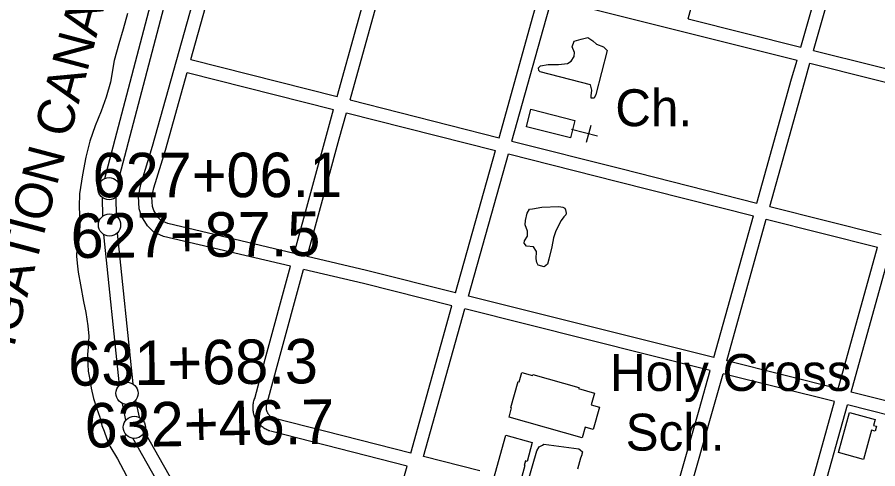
# Model space of a CAD drawing. Extents: x 3677843 to 3715951, y 511991 to 537744.
# Drawn here: x 3694073 to 3696008, y 532913 to 533929 of the extents above; entities that cross this region are included whole.
import ezdxf

# ---------------------------------------------------------------- set-up
doc = ezdxf.new("R2010")
doc.units = 0
for name, color, linetype in [('V-BLDG-IDEN', 7, 'Continuous'), ('V-BLDG-OTLN', 7, 'Continuous'), ('V-RIVR-IDEN', 7, 'Continuous'), ('V-ROAD-CNTR', 7, 'Continuous'), ('V-SITE-OTLN', 7, 'Continuous'), ('V-SITE-VEGE', 7, 'Continuous'), ('V-SURV-IDEN', 7, 'Continuous'), ('V-SURV-LINE', 7, 'Continuous'), ('V-TOPO-SHOR', 7, 'Continuous')]:
    doc.layers.add(name, color=color, linetype=linetype)

msp = doc.modelspace()

# ---------------------------------------------------------------- linework, layer by layer
at = {"layer": 'V-BLDG-OTLN'}
for points in [[(3695316.5, 533657.1), (3695217.7, 533682.2), (3695227.8, 533721.8), (3695326.6, 533696.6)], [(3695232, 533125.2), (3695335.4, 533095.7), (3695334.7, 533093.2), (3695371, 533082.8), (3695363.5, 533056.6), (3695382, 533051.3), (3695367.8, 533001.5), (3695349.7, 533006.7), (3695342.8, 532982.4), (3695178.6, 533029.3), (3695184.5, 533049.9), (3695182.4, 533050.5), (3695199.1, 533109), (3695201.8, 533108.3), (3695207.8, 533129.5), (3695231.5, 533122.9)], [(3695919.1, 532949.6), (3695944.2, 533039.7), (3696002.1, 533023.5), (3695998.4, 533010.2), (3696004.7, 533008.4), (3696001.6, 532997.3), (3695994, 532999.4), (3695975.7, 532933.8)], [(3695171.2, 532988.3), (3695231, 532972), (3695219.4, 532929.5), (3695215.6, 532930.6), (3695212.8, 532920.4), (3695214.5, 532919.9), (3695180.7, 532796.5), (3695206.7, 532789.4), (3695200.5, 532766.4), (3695202.4, 532765.9), (3695197.5, 532748), (3695135, 532765.1), (3695128.7, 532742.1), (3695104.8, 532748.6)]]:
    msp.add_lwpolyline(points, close=True, dxfattribs=at)
at = {"layer": 'V-ROAD-CNTR'}
for points in [[(3694687.5, 533368.4), (3694401.7, 533435.8), (3694379.9, 533445.5), (3694365.8, 533459.6), (3694352.4, 533481.1), (3694347.3, 533497.8), (3694345.3, 533526.4), (3694350.9, 533552.5), (3694377.1, 533638.5), (3694574, 534342.1), (3694720.7, 534876.6), (3694839.9, 535303.8)], [(3695863.5, 533854), (3695999.9, 534332.1)], [(3695581.6, 533924.9), (3695689.9, 534322.7)], [(3695834.4, 533861.4), (3695945.4, 534250.6)], [(3694462.9, 533833.7), (3694551.3, 534149.9)], [(3694792.1, 533750.1), (3694880.8, 534069.4)], [(3694821.1, 533742.7), (3694909.9, 534062.3)], [(3695156.2, 533657.7), (3695233.2, 533933), (3695245.9, 533978.2)], [(3695185.3, 533650.3), (3695262.1, 533924.9), (3695275, 533970.9)], [(3695275, 533970.9), (3695826.2, 533832.5)], [(3695581.6, 533924.9), (3695834.4, 533861.4)], [(3695863.5, 533854), (3696002.1, 533819.2), (3696113.8, 533791.4)], [(3694462.9, 533833.7), (3694792.1, 533750.1)], [(3695736.1, 533510.7), (3695814.1, 533790.1), (3695826.2, 533832.5)], [(3695765.2, 533503.3), (3695843, 533782), (3695855.3, 533825.2)], [(3695855.3, 533825.2), (3695994.8, 533790.1), (3696105.7, 533762.5)], [(3694695.4, 533397.4), (3694411.3, 533464.4), (3694397.2, 533470.6), (3694389.5, 533478.4), (3694380, 533493.7), (3694377, 533503.3), (3694375.6, 533524.3), (3694380, 533545), (3694405.9, 533630), (3694454.8, 533804.8)], [(3694454.8, 533804.8), (3694784, 533721.2)], [(3694821.1, 533742.7), (3695156.2, 533657.7)], [(3694695.4, 533397.4), (3694767.9, 533663.2), (3694784, 533721.2)], [(3694724.7, 533390.5), (3694796.8, 533655.2), (3694813.1, 533713.8)], [(3694813.1, 533713.8), (3695148.1, 533628.8)], [(3695185.3, 533650.3), (3695430.2, 533588.1), (3695736.1, 533510.7)], [(3695058.5, 533308.7), (3695148.1, 533628.8)], [(3695087.6, 533301.4), (3695177.2, 533621.4)], [(3695177.2, 533621.4), (3695422.8, 533559), (3695728, 533481.8)], [(3695765.2, 533503.3), (3696015.6, 533440)], [(3695639, 533163), (3695728, 533481.8)], [(3695668.1, 533155.7), (3695757.1, 533474.4)], [(3695757.1, 533474.4), (3696007.5, 533411.1)], [(3695918.6, 533092.9), (3696007.5, 533411.1)], [(3695947.7, 533085.6), (3696036.6, 533403.7)], [(3695058.5, 533308.7), (3694858.5, 533358.9), (3694724.7, 533390.5)], [(3694606.9, 533071.1), (3694630.6, 533159.6), (3694687.5, 533368.4)], [(3694635.8, 533063.3), (3694659.6, 533151.8), (3694716.8, 533361.5)], [(3695050.4, 533279.8), (3694851.5, 533329.8), (3694716.8, 533361.5)], [(3695639, 533163), (3695087.6, 533301.4)], [(3694957.5, 532947.9), (3695050.4, 533279.8)], [(3694986.6, 532940.5), (3695079.5, 533272.5)], [(3695631, 533134.1), (3695079.5, 533272.5)], [(3695918.6, 533092.9), (3695668.1, 533155.7)], [(3695353.6, 532160.4), (3695606.2, 533045.3), (3695631, 533134.1)], [(3695567.2, 532799.5), (3695635, 533037.1), (3695660.1, 533126.8)], [(3695910.5, 533064), (3695660.1, 533126.8)], [(3694640.5, 532997.9), (3694638.4, 532998.6), (3694636.2, 532999.6), (3694633.9, 533000.6), (3694631.7, 533001.8), (3694629.6, 533003.1), (3694627.5, 533004.4), (3694625.5, 533005.8), (3694623.6, 533007.4), (3694621.7, 533009), (3694619.9, 533010.7), (3694618.1, 533012.5), (3694616.5, 533014.3), (3694614.9, 533016.2), (3694613.4, 533018.2), (3694612, 533020.2), (3694610.7, 533022.4), (3694609.5, 533024.5), (3694608.4, 533026.7), (3694607.4, 533029), (3694606.5, 533031.3), (3694605.7, 533033.6), (3694605, 533036), (3694604.4, 533038.4), (3694603.9, 533040.8), (3694603.5, 533043.3), (3694603.2, 533045.7), (3694603, 533048.2), (3694603, 533050.7), (3694603, 533053.2), (3694603.2, 533055.6), (3694603.4, 533058.1), (3694603.8, 533060.5), (3694604.3, 533063), (3694604.9, 533065.4), (3694605.6, 533067.8), (3694606.4, 533070.1), (3694607.2, 533072.3), (3694607.5, 533073.1)], [(3696200.1, 533022.6), (3696094.8, 533048.6), (3695947.7, 533085.6)], [(3694650.9, 533026), (3694649.5, 533026.5), (3694648.5, 533026.9), (3694647.4, 533027.4), (3694646.4, 533028), (3694645.4, 533028.6), (3694644.4, 533029.2), (3694643.5, 533029.9), (3694642.6, 533030.6), (3694641.7, 533031.3), (3694640.9, 533032.1), (3694640.1, 533033), (3694639.3, 533033.8), (3694638.6, 533034.7), (3694637.9, 533035.6), (3694637.2, 533036.6), (3694636.6, 533037.6), (3694636, 533038.6), (3694635.5, 533039.6), (3694635.1, 533040.7), (3694634.6, 533041.7), (3694634.2, 533042.8), (3694633.9, 533043.9), (3694633.6, 533045.1), (3694633.4, 533046.2), (3694633.2, 533047.3), (3694633.1, 533048.5), (3694633, 533049.6), (3694633, 533050.8), (3694633, 533051.9), (3694633.1, 533053.1), (3694633.2, 533054.2), (3694633.4, 533055.4), (3694633.6, 533056.5), (3694633.9, 533057.6), (3694634.2, 533058.7), (3694634.6, 533059.8), (3694635, 533061), (3694635.2, 533061.3)], [(3695818.9, 532737.8), (3695854.7, 532864.2), (3695910.5, 533064)], [(3695848, 532730.6), (3695883.5, 532856.1), (3695939.6, 533056.6)], [(3696192, 532993.7), (3696087.5, 533019.5), (3695939.6, 533056.6)], [(3694957.5, 532947.9), (3694649.4, 533026.5)], [(3694949.4, 532919), (3694642, 532997.4)], [(3695113.3, 532908.2), (3694986.6, 532940.5)], [(3694821.7, 532475.1), (3694925.7, 532834.1), (3694949.4, 532919)]]:
    msp.add_lwpolyline(points, dxfattribs=at)
at = {"layer": 'V-SITE-OTLN'}
for p, q in [((3695319.4, 533677.3), (3695377.3, 533661.8)), ((3695352.8, 533647.6), (3695363.2, 533686.3))]:
    msp.add_line(p, q, dxfattribs=at)
at = {"layer": 'V-SITE-VEGE'}
for points in [[(3695248.3, 533806.2), (3695245.3, 533809.1), (3695244.6, 533815), (3695249.3, 533819.2), (3695266.9, 533822.5), (3695290, 533822.3), (3695310, 533824.9), (3695318.2, 533829.8), (3695325.1, 533840.5), (3695326.1, 533849.4), (3695320.6, 533862.3), (3695325.1, 533875.3), (3695340.9, 533879.7), (3695356.2, 533882.9), (3695367, 533876), (3695375.3, 533868.5), (3695391.4, 533862.3), (3695399.2, 533854.1), (3695374.2, 533754.6), (3695370.2, 533746.9), (3695363.2, 533746.8), (3695363.1, 533752.1), (3695365.2, 533764.5), (3695362.1, 533776.8)], [(3695291, 533503.1), (3695295.2, 533502), (3695299.3, 533501.5), (3695304.1, 533499.2), (3695305.9, 533495.1), (3695307.2, 533488), (3695306.1, 533484.5), (3695302, 533479.7), (3695295.7, 533471.3), (3695283.7, 533448.1), (3695278.6, 533432.7), (3695274.8, 533412), (3695268.2, 533384.2), (3695264.8, 533373.5), (3695257.8, 533367.5), (3695244.2, 533370.8), (3695241.2, 533376.6), (3695239.9, 533384.9), (3695240.2, 533402), (3695233.5, 533411.9), (3695217.6, 533414), (3695212.7, 533420.4), (3695213.8, 533425.7), (3695220.2, 533435.9), (3695220.5, 533447.7), (3695215, 533461.8), (3695216, 533471.8), (3695219.3, 533487.8), (3695224.5, 533496.7), (3695231.5, 533498), (3695252.1, 533501.3)]]:
    msp.add_lwpolyline(points, close=True, dxfattribs=at)
msp.add_lwpolyline([(3695199.1, 532807.8), (3695241, 532953), (3695246.7, 532962.6), (3695253.8, 532966.2), (3695256.7, 532968), (3695335.3, 532957.5), (3695338.9, 532955.8), (3695343.7, 532951.2), (3695342.6, 532945.8), (3695342, 532944.1), (3695339.2, 532936.4), (3695332.5, 532912.1)], dxfattribs=at)
at = {"layer": 'V-SURV-LINE'}
for points in [[(3694269.9, 533566), (3694483.6, 534379.8)], [(3694512.6, 534372.1), (3694299, 533558.4)], [(3694265.1, 533481.3), (3694264.6, 533522.7)], [(3694294.6, 533523.1), (3694295.1, 533481.7)], [(3694302.7, 533101.1), (3694267.5, 533440.1)], [(3694297.3, 533443.2), (3694332.5, 533104.2)], [(3694317.4, 533022.5), (3694309.2, 533060)], [(3694338.6, 533066.4), (3694346.7, 533028.9)], [(3694359.2, 532996.2), (3694768.3, 532272.6)], [(3694742.1, 532257.9), (3694333.1, 532981.4)]]:
    msp.add_lwpolyline(points, dxfattribs=at)
for centre in [(3694279.4, 533542.9), (3694280.4, 533461.5), (3694319.6, 533082.7), (3694336.3, 533006.2)]:
    msp.add_circle(centre, 25, dxfattribs=at)
at = {"layer": 'V-TOPO-SHOR'}
msp.add_lwpolyline([(3694320.7, 533937.1), (3694311.4, 533902), (3694301.2, 533868.8), (3694291, 533831.2), (3694282.3, 533782.5), (3694273, 533749.3), (3694261.4, 533717.7), (3694248, 533684.2), (3694235.9, 533649.7), (3694226.9, 533614), (3694219.3, 533574.5), (3694212.7, 533531.5), (3694212.2, 533502.6), (3694213.5, 533465.8), (3694213.2, 533443), (3694209.7, 533422.9), (3694206.8, 533406.7), (3694206.4, 533391.4), (3694207.6, 533375.6), (3694210.2, 533355), (3694214.8, 533326.8), (3694222, 533289.2), (3694227.2, 533264.5), (3694231.8, 533234.4), (3694233.5, 533210.9), (3694232.3, 533186.8), (3694231, 533169.6), (3694231.3, 533147.7), (3694232.2, 533132.5), (3694236, 533113.5), (3694238.9, 533094.2), (3694244, 533071.1), (3694251.3, 533050), (3694258.7, 533028.8), (3694263.4, 533010.5), (3694268.1, 532997.5), (3694274.7, 532980.5), (3694281.3, 532964.1), (3694298.3, 532935.2), (3694325.1, 532884.5)], dxfattribs=at)

# ---------------------------------------------------------------- texts
at = {"layer": 'V-BLDG-IDEN'}
for s, p in [('Ch.', (3695417.6, 533683.6)), ('Holy Cross', (3695405.9, 533088)), ('Sch.', (3695440.8, 532953.8))]:
    msp.add_text(s, height=83, dxfattribs=at).set_placement(p)
at = {"layer": 'V-RIVR-IDEN'}
msp.add_text('NAVIGATION CANAL', height=83, rotation=75.1009, dxfattribs=at).set_placement((3694006.3, 532963.3))
at = {"layer": 'V-SURV-IDEN'}
for s, rotation, p in [('   627+06.1   ', 0.0386, (3694130.7, 533523.6)), ('   627+87.5   ', 0.5036, (3694081.9, 533386)), ('   631+68.3   ', 0.5853, (3694076.4, 533098.4)), ('   632+46.7   ', 0.9646, (3694113.7, 532958.3))]:
    msp.add_text(s, height=100, rotation=rotation, dxfattribs=at).set_placement(p)

doc.saveas('drawing.dxf')
